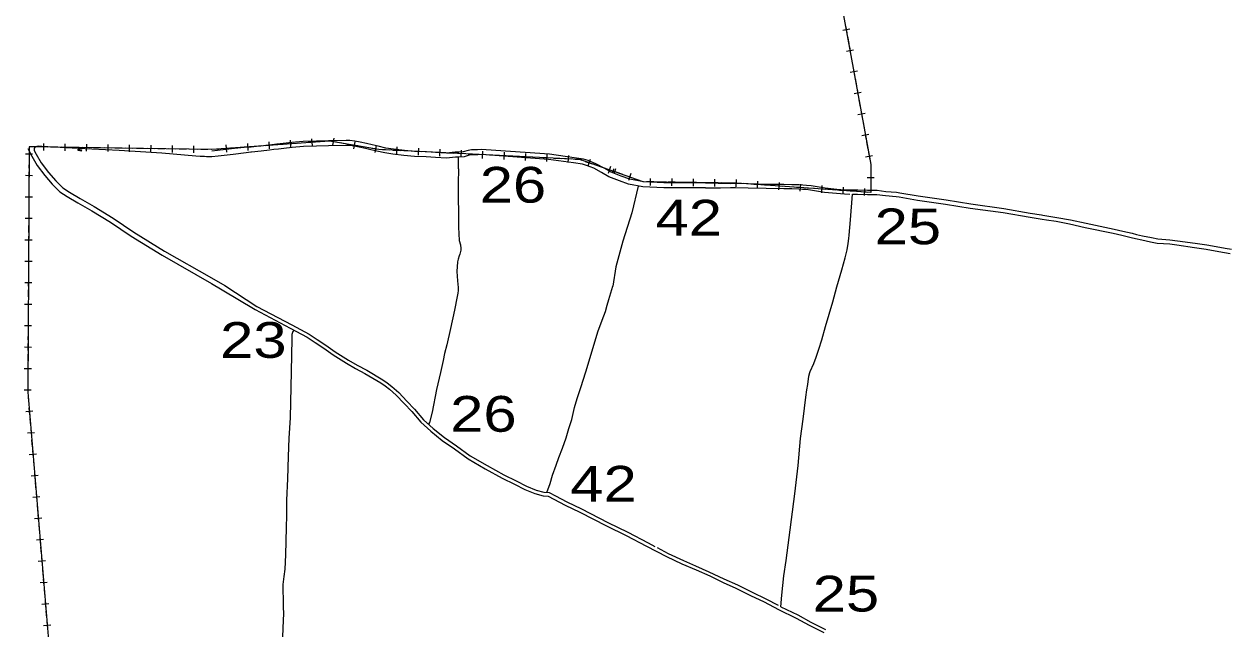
# Model space of a CAD drawing. Extents: x 476989 to 498418, y 4381813 to 4416555.
# Drawn here: x 483846 to 485532, y 4387137 to 4387982 of the extents above; entities that cross this region are included whole.
import ezdxf
from ezdxf.enums import TextEntityAlignment as Align

# ---------------------------------------------------------------- set-up
doc = ezdxf.new("R2010")
doc.units = 0
doc.header["$LTSCALE"] = 20
for name, color, linetype, lineweight in [('13', 7, 'Continuous', 13), ('34', 7, 'Continuous', 13), ('36', 7, 'Continuous', 13), ('38', 7, 'Continuous', 13), ('47', 7, 'Continuous', 13), ('6', 7, 'Continuous', 25)]:
    doc.layers.add(name, color=color, linetype=linetype, lineweight=lineweight)

msp = doc.modelspace()

# ---------------------------------------------------------------- linework, layer by layer
at = {"layer": '34'}
for p, q in [((484990.85, 4387974.21), (485000.69, 4387975.99)), ((484994.88, 4387980.02), (484996.66, 4387970.18)), ((484997.55, 4387965.26), (484999.33, 4387955.42)), ((484996.19, 4387944.69), (485006.03, 4387946.47)), ((485000.22, 4387950.5), (485002, 4387940.66)), ((485002.89, 4387935.74), (485004.67, 4387925.9)), ((485005.56, 4387920.98), (485007.35, 4387911.14)), ((485001.54, 4387915.17), (485011.38, 4387916.95)), ((485008.24, 4387906.22), (485010.02, 4387896.38)), ((485006.88, 4387885.65), (485016.72, 4387887.43)), ((485010.91, 4387891.46), (485012.69, 4387881.62)), ((485013.58, 4387876.7), (485015.36, 4387866.86)), ((485012.22, 4387856.13), (485022.06, 4387857.91)), ((485016.25, 4387861.94), (485018.03, 4387852.1)), ((485018.92, 4387847.18), (485020.71, 4387837.34)), ((484188.13, 4387817.84), (484188.85, 4387807.87)), ((484218.05, 4387820.02), (484218.77, 4387810.04)), ((484247.97, 4387822.19), (484248.69, 4387812.22)), ((484268.28, 4387818.66), (484258.3, 4387817.93)), ((484283.11, 4387817.24), (484273.26, 4387818.95)), ((484279.04, 4387823.02), (484277.33, 4387813.17)), ((484308.6, 4387817.88), (484306.89, 4387808.03)), ((485017.57, 4387826.61), (485027.41, 4387828.39)), ((485021.6, 4387832.42), (485023.38, 4387822.58)), ((485024.27, 4387817.66), (485026.05, 4387807.82)), ((483847.94, 4387801.06), (483857.94, 4387801)), ((483852.97, 4387806.03), (483852.91, 4387796.03)), ((483863.03, 4387810.84), (483853.03, 4387811)), ((483878.03, 4387810.61), (483868.03, 4387810.76)), ((483873.11, 4387815.69), (483872.95, 4387805.69)), ((483893.03, 4387810.37), (483883.03, 4387810.53)), ((483908.02, 4387810.14), (483898.03, 4387810.29)), ((483903.1, 4387815.21), (483902.95, 4387805.22)), ((483923.02, 4387809.9), (483913.02, 4387810.06)), ((483938.02, 4387809.67), (483928.02, 4387809.82)), ((483933.1, 4387814.74), (483932.94, 4387804.75)), ((483953.02, 4387809.43), (483943.02, 4387809.59)), ((483968.02, 4387809.2), (483958.02, 4387809.35)), ((483963.1, 4387814.27), (483962.94, 4387804.27)), ((483983.02, 4387808.96), (483973.02, 4387809.12)), ((483998.01, 4387808.73), (483988.01, 4387808.88)), ((483993.09, 4387813.8), (483992.94, 4387803.8)), ((484013.01, 4387808.49), (484003.01, 4387808.65)), ((484028.01, 4387808.25), (484018.01, 4387808.41)), ((484023.09, 4387813.33), (484022.93, 4387803.33)), ((484043.01, 4387808.02), (484033.01, 4387808.18)), ((484058.01, 4387807.78), (484048.01, 4387807.94)), ((484053.09, 4387812.86), (484052.93, 4387802.86)), ((484073, 4387807.55), (484063.01, 4387807.71)), ((484088, 4387807.31), (484078, 4387807.47)), ((484083.08, 4387812.39), (484082.92, 4387802.39)), ((484103, 4387807.08), (484093, 4387807.24)), ((484108.44, 4387807.03), (484108, 4387807)), ((484118.67, 4387807.78), (484108.7, 4387807.05)), ((484133.63, 4387808.86), (484123.66, 4387808.14)), ((484128.28, 4387813.49), (484129.01, 4387803.51)), ((484148.59, 4387809.95), (484138.62, 4387809.23)), ((484163.55, 4387811.04), (484153.58, 4387810.32)), ((484158.21, 4387815.66), (484158.93, 4387805.69)), ((484178.52, 4387812.13), (484168.54, 4387811.4)), ((484193.48, 4387813.22), (484183.5, 4387812.49)), ((484208.44, 4387814.3), (484198.46, 4387813.58)), ((484223.4, 4387815.39), (484213.42, 4387814.67)), ((484238.36, 4387816.48), (484228.38, 4387815.76)), ((484253.32, 4387817.57), (484243.34, 4387816.84)), ((484297.89, 4387814.67), (484288.04, 4387816.38)), ((484312.67, 4387812.1), (484302.82, 4387813.81)), ((484327.45, 4387809.53), (484317.6, 4387811.24)), ((484338.16, 4387812.74), (484336.44, 4387802.89)), ((484357.21, 4387806.24), (484347.22, 4387806.74)), ((484372.19, 4387805.5), (484362.21, 4387805.99)), ((484367.45, 4387810.74), (484366.95, 4387800.75)), ((484387.17, 4387804.75), (484377.19, 4387805.25)), ((484402.16, 4387804), (484392.17, 4387804.5)), ((484397.41, 4387809.25), (484396.91, 4387799.26)), ((484417.14, 4387803.26), (484407.15, 4387803.75)), ((484432.12, 4387802.51), (484422.13, 4387803.01)), ((484427.37, 4387807.75), (484426.88, 4387797.77)), ((484447.1, 4387801.76), (484437.11, 4387802.26)), ((484462.08, 4387801.02), (484452.09, 4387801.51)), ((484457.34, 4387806.26), (484456.84, 4387796.27)), ((484487.3, 4387804.77), (484486.8, 4387794.78)), ((484517.26, 4387803.27), (484516.76, 4387793.29)), ((484547.22, 4387801.78), (484546.73, 4387791.79)), ((485026.94, 4387802.9), (485028.72, 4387793.06)), ((483852.88, 4387791.03), (483852.83, 4387781.03)), ((484477.06, 4387800.27), (484467.08, 4387800.77)), ((484492.04, 4387799.52), (484482.06, 4387800.02)), ((484507.03, 4387798.78), (484497.04, 4387799.28)), ((484522.01, 4387798.03), (484512.02, 4387798.53)), ((484536.99, 4387797.29), (484527, 4387797.78)), ((484551.97, 4387796.54), (484541.98, 4387797.04)), ((484566.95, 4387795.79), (484556.96, 4387796.29)), ((484581.93, 4387795.05), (484571.95, 4387795.54)), ((484577.19, 4387800.29), (484576.69, 4387790.3)), ((484596.91, 4387794.3), (484586.93, 4387794.8)), ((484611.9, 4387793.55), (484601.91, 4387794.05)), ((484607.15, 4387798.8), (484606.65, 4387788.81)), ((484640.83, 4387786.79), (484631.39, 4387790.08)), ((484637.75, 4387793.16), (484634.46, 4387783.71)), ((484655, 4387781.86), (484645.55, 4387785.14)), ((485022.91, 4387797.09), (485032.75, 4387798.87)), ((483847.77, 4387771.06), (483857.77, 4387771)), ((483852.8, 4387776.03), (483852.74, 4387766.03)), ((484669.16, 4387776.92), (484659.72, 4387780.21)), ((484666.08, 4387783.29), (484662.8, 4387773.84)), ((484683.33, 4387771.99), (484673.88, 4387775.28)), ((484697.49, 4387767.05), (484688.05, 4387770.34)), ((484694.42, 4387773.42), (484691.13, 4387763.98)), ((485025, 4387768.17), (485035, 4387768.17)), ((485030, 4387773.17), (485030, 4387763.17)), ((483852.71, 4387761.03), (483852.65, 4387751.03)), ((484711.66, 4387762.12), (484702.21, 4387765.41)), ((484726.64, 4387761.78), (484716.64, 4387761.93)), ((484721.71, 4387766.85), (484721.56, 4387756.85)), ((484741.63, 4387761.55), (484731.64, 4387761.7)), ((484756.63, 4387761.32), (484746.63, 4387761.47)), ((484751.71, 4387766.39), (484751.56, 4387756.4)), ((484771.63, 4387761.09), (484761.63, 4387761.24)), ((484786.63, 4387760.86), (484776.63, 4387761.01)), ((484781.71, 4387765.94), (484781.55, 4387755.94)), ((484801.63, 4387760.63), (484791.63, 4387760.78)), ((484816.63, 4387760.4), (484806.63, 4387760.56)), ((484811.7, 4387765.48), (484811.55, 4387755.48)), ((484831.62, 4387760.17), (484821.62, 4387760.33)), ((484841.7, 4387765.02), (484841.55, 4387755.02)), ((484861.58, 4387758.71), (484851.6, 4387759.4)), ((484876.54, 4387757.67), (484866.57, 4387758.36)), ((484871.9, 4387763), (484871.21, 4387753.03)), ((484891.5, 4387756.63), (484881.53, 4387757.32)), ((484906.47, 4387755.59), (484896.49, 4387756.28)), ((484901.83, 4387760.92), (484901.13, 4387750.95)), ((484921.43, 4387754.55), (484911.46, 4387755.24)), ((484936.4, 4387753.51), (484926.42, 4387754.2)), ((484931.76, 4387758.84), (484931.06, 4387748.87)), ((484951.36, 4387752.47), (484941.38, 4387753.16)), ((484966.32, 4387751.43), (484956.35, 4387752.12)), ((484961.68, 4387756.76), (484960.99, 4387746.79)), ((484981.29, 4387750.39), (484971.31, 4387751.08)), ((484991.61, 4387754.68), (484990.92, 4387744.7)), ((485021.54, 4387752.6), (485020.85, 4387742.62)), ((485030, 4387758.17), (485030, 4387748.17)), ((483847.59, 4387741.06), (483857.59, 4387741)), ((483852.62, 4387746.03), (483852.56, 4387736.03)), ((484996.25, 4387749.35), (484986.28, 4387750.04)), ((485011.22, 4387748.31), (485001.24, 4387749)), ((485026.18, 4387747.27), (485016.2, 4387747.96)), ((483852.53, 4387731.03), (483852.48, 4387721.03)), ((483847.42, 4387711.06), (483857.42, 4387711)), ((483852.36, 4387701.03), (483852.3, 4387691.03)), ((483852.45, 4387716.03), (483852.39, 4387706.03)), ((483852.27, 4387686.03), (483852.21, 4387676.03)), ((483847.24, 4387681.06), (483857.24, 4387681)), ((483852.18, 4387671.03), (483852.13, 4387661.03)), ((483847.07, 4387651.06), (483857.07, 4387651)), ((483852.1, 4387656.03), (483852.04, 4387646.03)), ((483852.01, 4387641.03), (483851.95, 4387631.03)), ((483846.89, 4387621.06), (483856.89, 4387621.01)), ((483851.92, 4387626.03), (483851.86, 4387616.03)), ((483851.83, 4387611.03), (483851.78, 4387601.03)), ((483846.72, 4387591.06), (483856.72, 4387591.01)), ((483851.75, 4387596.04), (483851.69, 4387586.04)), ((483851.57, 4387566.04), (483851.51, 4387556.04)), ((483851.66, 4387581.04), (483851.6, 4387571.04)), ((483846.54, 4387561.06), (483856.54, 4387561.01)), ((483851.48, 4387551.04), (483851.43, 4387541.04)), ((483846.37, 4387531.07), (483856.37, 4387531.01)), ((483851.4, 4387536.04), (483851.34, 4387526.04)), ((483851.31, 4387521.04), (483851.25, 4387511.04)), ((483846.19, 4387501.07), (483856.19, 4387501.01)), ((483851.22, 4387506.04), (483851.16, 4387496.04)), ((483851.13, 4387491.04), (483851.08, 4387481.04)), ((483846.02, 4387471.07), (483856.02, 4387471.01)), ((483851.58, 4387461.06), (483852.41, 4387451.1)), ((483848.26, 4387440.71), (483858.23, 4387441.55)), ((483852.83, 4387446.11), (483853.66, 4387436.15)), ((483854.08, 4387431.17), (483854.91, 4387421.2)), ((483855.33, 4387416.22), (483856.16, 4387406.25)), ((483850.76, 4387410.82), (483860.72, 4387411.65)), ((483856.57, 4387401.27), (483857.41, 4387391.3)), ((483853.26, 4387380.92), (483863.22, 4387381.76)), ((483857.82, 4387386.32), (483858.65, 4387376.36)), ((483859.07, 4387371.37), (483859.9, 4387361.41)), ((483855.75, 4387351.03), (483865.72, 4387351.86)), ((483860.32, 4387356.43), (483861.15, 4387346.46)), ((483861.57, 4387341.48), (483862.4, 4387331.51)), ((483858.25, 4387321.13), (483868.22, 4387321.96)), ((483862.82, 4387326.53), (483863.65, 4387316.56)), ((483864.07, 4387311.58), (483864.9, 4387301.62)), ((483865.31, 4387296.63), (483866.15, 4387286.67)), ((483860.75, 4387291.24), (483870.71, 4387292.07)), ((483866.56, 4387281.69), (483867.39, 4387271.72)), ((483863.24, 4387261.34), (483873.21, 4387262.17)), ((483867.81, 4387266.74), (483868.64, 4387256.77)), ((483869.06, 4387251.79), (483869.89, 4387241.82)), ((483865.74, 4387231.44), (483875.71, 4387232.28)), ((483870.31, 4387236.84), (483871.14, 4387226.88)), ((483871.56, 4387221.89), (483872.39, 4387211.93)), ((483868.24, 4387201.55), (483878.2, 4387202.38)), ((483872.8, 4387206.95), (483873.64, 4387196.98)), ((483874.05, 4387192), (483874.89, 4387182.03)), ((483875.3, 4387177.05), (483876.13, 4387167.09)), ((483870.74, 4387171.65), (483880.7, 4387172.48)), ((483876.55, 4387162.1), (483877.38, 4387152.14)), ((483877.8, 4387147.15), (483878.63, 4387137.19)), ((483873.23, 4387141.76), (483883.2, 4387142.59))]:
    msp.add_line(p, q, dxfattribs=at)
for points in [[(484742, 4388368), (484968, 4388081), (484988, 4388018), (485030, 4387786), (485030, 4387747), (484843, 4387760), (484712, 4387762), (484623, 4387793), (484342, 4387807), (484273, 4387819), (484108.44, 4387807.03)], [(484108, 4387807), (483853, 4387811), (483851, 4387468), (483887, 4387037), (483872.5, 4386448.65)], [(484342.23, 4387806.99), (484342, 4387807), (484332.37, 4387808.67)], [(484626.67, 4387791.72), (484623, 4387793), (484616.89, 4387793.3)], [(485029.61, 4387788.14), (485030, 4387786), (485030, 4387778.17)], [(484846.61, 4387759.75), (484843, 4387760), (484836.62, 4387760.1)], [(483851.05, 4387476.04), (483851, 4387468), (483851.16, 4387466.04)]]:
    msp.add_lwpolyline(points, dxfattribs=at)
at = {"layer": '36'}
for p, q in [((484108.03, 4387619.81), (484123.22, 4387611.07)), ((484108.05, 4387627.5), (484126.55, 4387616.86))]:
    msp.add_line(p, q, dxfattribs=at)
for points in [[(484492.14, 4387806.72), (484486.14, 4387806.96), (484480.32, 4387806.84), (484476.34, 4387806.76), (484471.87, 4387806.54), (484467.1, 4387806), (484460.07, 4387803.89), (484453.81, 4387803.31), (484448.89, 4387803.21), (484436.69, 4387802.24), (484421.56, 4387802.76), (484408.78, 4387803.86), (484392.62, 4387804.33), (484377.91, 4387805.83), (484362.6, 4387807.61), (484351.87, 4387809.25), (484341.04, 4387811.67), (484332.68, 4387813.54), (484324.9, 4387815.4), (484316.04, 4387817.5), (484308.68, 4387818.74), (484301.73, 4387819.68), (484296.23, 4387819.57), (484271.85, 4387819.17), (484254.85, 4387819.04), (484236.24, 4387818.52), (484220.25, 4387816.99), (484208.34, 4387815.67), (484199.57, 4387814.74), (484192.4, 4387813.48), (484184.31, 4387812.87), (484177.12, 4387811.96), (484174.63, 4387811.68)], [(483851.03, 4387808.55), (483857.01, 4387797.7), (483864.1, 4387784.71), (483874.77, 4387770.68), (483885.4, 4387758.59), (483896.2, 4387748.15), (483906.03, 4387741.65), (483921.28, 4387732.7), (483940.8, 4387721.55), (483967.05, 4387705.4), (483995.93, 4387685.76), (484039.14, 4387659.45), (484108.03, 4387619.81)], [(483870.96, 4387811.4), (483866.44, 4387811.67), (483863.59, 4387811.57), (483861.49, 4387811.04), (483860.51, 4387809.56), (483860.05, 4387807.95), (483860.05, 4387806.82), (483860.27, 4387805.88)], [(483860.27, 4387805.88), (483862.88, 4387800.87), (483869.72, 4387788.35), (483879.94, 4387774.91), (483890.24, 4387763.2), (483900.4, 4387753.38), (483909.57, 4387747.32), (483924.63, 4387738.47), (483944.21, 4387727.3), (483970.67, 4387711.01), (483999.55, 4387691.37), (484042.54, 4387665.2), (484108.05, 4387627.5)], [(484108.42, 4387797.03), (484101.21, 4387797.11), (484098.2, 4387797.19), (484092.4, 4387797.41), (484086.08, 4387797.87), (484038.5, 4387802.12), (483979.17, 4387805.81), (483921.64, 4387808.76), (483870.96, 4387811.4)], [(484491.86, 4387799.73), (484486.07, 4387799.96), (484480.46, 4387799.85), (484476.58, 4387799.77), (484472.44, 4387799.57), (484468.51, 4387799.12), (484461.41, 4387796.99), (484454.21, 4387796.32), (484449.24, 4387796.22), (484436.85, 4387795.24), (484421.14, 4387795.78), (484408.38, 4387796.87), (484392.16, 4387797.35), (484377.15, 4387798.88), (484361.67, 4387800.68), (484350.58, 4387802.37), (484339.52, 4387804.85), (484331.1, 4387806.73), (484323.28, 4387808.6), (484314.65, 4387810.64), (484307.63, 4387811.82), (484301.33, 4387812.68), (484296.36, 4387812.58), (484271.93, 4387812.18), (484254.98, 4387812.05), (484236.67, 4387811.54), (484220.97, 4387810.03), (484209.3, 4387808.74), (484201.82, 4387807.75), (484195.07, 4387807.06), (484189.06, 4387806.36), (484177.76, 4387804.99), (484164.03, 4387803.43), (484162.95, 4387803.36), (484156.54, 4387802.4), (484138.3, 4387800.35), (484117.28, 4387798.01), (484108.42, 4387797.03)], [(484174.63, 4387811.68), (484163.41, 4387810.4), (484162.48, 4387810.34), (484153.9, 4387809.75), (484136.02, 4387807.99), (484116.51, 4387805.89), (484108.43, 4387804.72)], [(484798.93, 4387760.7), (484740.89, 4387760.52), (484712.35, 4387761.9), (484693.08, 4387765.5), (484681.23, 4387769.77), (484666.83, 4387775.25), (484657.12, 4387781), (484645.83, 4387787.32), (484634.93, 4387791.59), (484628.34, 4387793.7), (484615.13, 4387795.49), (484580.58, 4387800.8), (484492.14, 4387806.72)], [(484798.95, 4387753.61), (484740.73, 4387753.43), (484711.52, 4387754.84), (484691.22, 4387758.64), (484678.76, 4387763.13), (484663.74, 4387768.84), (484653.58, 4387774.86), (484642.8, 4387780.89), (484632.55, 4387784.9), (484626.77, 4387786.76), (484614.38, 4387788.44), (484579.29, 4387793.34), (484491.86, 4387799.73)], [(484798.93, 4387760.7), (484834.03, 4387759.68), (484840.94, 4387759.89), (484858.69, 4387759.43), (484883.86, 4387758.86), (484908.49, 4387758.47), (484919.79, 4387758.31), (484929.83, 4387758.04), (484934.93, 4387757.78), (484940.17, 4387757.35), (484946.81, 4387756.64), (484966.32, 4387753.46), (484982.82, 4387751.87), (484993.84, 4387750.94), (485001.08, 4387750.58), (485011.81, 4387750.66), (485025.45, 4387750.29), (485038.89, 4387750.19), (485051.42, 4387748.65), (485066.32, 4387747.42), (485070.86, 4387746.77), (485096.5, 4387742.28), (485135.5, 4387736.71), (485170.14, 4387731.03), (485216.24, 4387724.72), (485253.12, 4387718.26), (485268.79, 4387715.93), (485270.96, 4387715.52), (485290.18, 4387712.13), (485309.62, 4387708.84), (485331.43, 4387704.04), (485370.49, 4387695.9), (485382.54, 4387692.96), (485395.76, 4387690.01), (485401.7, 4387688.38), (485410.35, 4387686.48), (485422.59, 4387683.93), (485431.58, 4387682.19), (485448.2, 4387681.05)], [(484798.95, 4387753.61), (484820.12, 4387753.58), (484834.17, 4387753.81), (484840.95, 4387754.01), (484858.55, 4387753.56), (484883.74, 4387752.99), (484908.41, 4387752.6), (484919.67, 4387752.44), (484929.6, 4387752.17), (484934.54, 4387751.92), (484939.61, 4387751.5), (484946.03, 4387750.81), (484965.57, 4387747.63), (484982.29, 4387746.02), (484993.45, 4387745.08), (485000.69, 4387744.72)], [(485004.65, 4387744.73), (485011.76, 4387744.78), (485025.35, 4387744.41), (485038.51, 4387744.32), (485050.82, 4387742.8), (485065.65, 4387741.58), (485069.93, 4387740.96), (485095.58, 4387736.47), (485134.61, 4387730.9), (485169.26, 4387725.22), (485215.38, 4387718.9), (485253.12, 4387712.35), (485269.91, 4387709.7), (485276.03, 4387708.96), (485289.33, 4387706.75), (485308.29, 4387703.12), (485330.2, 4387698.29), (485369.19, 4387690.16), (485381.21, 4387687.24), (485394.34, 4387684.31), (485400.29, 4387682.67), (485409.12, 4387680.73), (485421.43, 4387678.16), (485430.75, 4387676.36), (485448.2, 4387675.12)], [(485448.2, 4387681.05), (485458.98, 4387679.52), (485483.62, 4387676.09), (485499.96, 4387673.83), (485513.05, 4387671.47), (485525.85, 4387669.03), (485534.71, 4387667.62)], [(485448.2, 4387675.12), (485458.17, 4387673.7), (485482.82, 4387670.27), (485499.03, 4387668.02), (485511.98, 4387665.69), (485524.84, 4387663.24), (485532.77, 4387661.98)], [(484126.55, 4387616.86), (484171.56, 4387587.69), (484220.56, 4387561.88), (484244.55, 4387549.14), (484255.68, 4387541.67), (484268.12, 4387533.64), (484280.94, 4387524.46), (484299.66, 4387512.73), (484312.04, 4387505.62), (484325.17, 4387498.5), (484347.5, 4387485.15), (484353.9, 4387480.89), (484360.39, 4387475.99), (484369.97, 4387467.47), (484381.34, 4387455.3), (484391.96, 4387444.02), (484404.4, 4387429.24), (484417.97, 4387417.02), (484433.78, 4387404.44), (484450.68, 4387392.61), (484469.89, 4387379.04), (484493.44, 4387365.2), (484517.03, 4387352.17), (484534.33, 4387343.66), (484548.49, 4387336.61), (484562.01, 4387330.96), (484572.76, 4387328.16), (484580.5, 4387327.48), (484589.4, 4387322.8), (484605.22, 4387314.52), (484625.5, 4387304.54), (484662.61, 4387285.63)], [(484123.22, 4387611.07), (484169.09, 4387583.22), (484218.18, 4387557.37), (484241.92, 4387544.76), (484252.87, 4387537.41), (484265.25, 4387529.42), (484278.09, 4387520.22), (484297.03, 4387508.36), (484309.55, 4387501.16), (484322.57, 4387494.1), (484344.86, 4387480.78), (484350.95, 4387476.73), (484357.15, 4387472.04), (484366.41, 4387463.82), (484377.62, 4387451.81), (484388.15, 4387440.62), (484400.73, 4387425.69), (484414.67, 4387413.12), (484430.73, 4387400.34), (484447.75, 4387388.44), (484467.12, 4387374.75), (484490.91, 4387360.77), (484514.67, 4387347.64), (484532.07, 4387339.08), (484546.36, 4387331.96), (484560.38, 4387326.12), (484571.88, 4387323.12), (484579.03, 4387322.49), (484587.03, 4387318.28), (484602.91, 4387309.97), (484623.22, 4387299.98), (484660.3, 4387281.08)], [(484660.3, 4387281.08), (484688, 4387267.44), (484716.6, 4387252.46), (484744.57, 4387237.87), (484765.96, 4387228.04), (484785.95, 4387219.5), (484804.94, 4387211.05), (484823.92, 4387201.9), (484841.33, 4387193.76), (484861.92, 4387183.47), (484880.95, 4387174.47), (484900.92, 4387163.88), (484925.9, 4387151.85), (484944.1, 4387141.99), (484964.47, 4387131.61)], [(484662.61, 4387285.63), (484690.3, 4387271.97), (484718.95, 4387256.96), (484728.09, 4387252.19)], [(484731.26, 4387250.54), (484746.8, 4387242.43), (484768.02, 4387232.68), (484785.12, 4387224.95), (484803.58, 4387216.58), (484824.62, 4387206.9), (484843.61, 4387198.29), (484864.14, 4387188.04), (484883.22, 4387179.01), (484900.49, 4387169.86)], [(484904.27, 4387167.9), (484928.21, 4387156.37), (484946.46, 4387146.48), (484966.73, 4387136.15)]]:
    msp.add_lwpolyline(points, dxfattribs=at)
at = {"layer": '38'}
for points in [[(484670.16, 4387780.04), (484669.72, 4387777.82), (484669.1, 4387775.84), (484668.65, 4387774.56)], [(484672.94, 4387780.04), (484672.11, 4387777.17), (484671.45, 4387775.07), (484670.96, 4387773.68)]]:
    msp.add_lwpolyline(points, dxfattribs=at)
at = {"layer": '47'}
msp.add_lwpolyline([(483921.8, 4387807.72), (483926.14, 4387806.91), (483925.75, 4387804.81), (483921.41, 4387805.62)], close=True, dxfattribs=at)
at = {"layer": '6'}
for points in [[(484453.47, 4387780.04), (484453.47, 4387780.1), (484453.58, 4387783.24), (484453.64, 4387789.5), (484453.63, 4387794.48), (484453.5, 4387796.31)], [(484453.47, 4387780.04), (484453.08, 4387759.69), (484453.48, 4387698.54), (484454.48, 4387679.81), (484456.12, 4387674), (484456.9, 4387668.86), (484456.87, 4387666.47), (484455.63, 4387660.65), (484454.55, 4387658.51), (484452.98, 4387653.95), (484452.22, 4387649.97), (484451.33, 4387636.56), (484451.92, 4387623.52)], [(484704.97, 4387756.07), (484696.13, 4387718.73), (484683.45, 4387678.89), (484673.62, 4387643.09), (484669.2, 4387615.95)], [(484904.27, 4387167.9), (484905.66, 4387183.86), (484908.57, 4387210.82), (484911.66, 4387232.66), (484916.02, 4387264.71), (484923.85, 4387325.72), (484928.6, 4387365.22), (484931.97, 4387402.9), (484935.53, 4387430.32), (484939.12, 4387461.07), (484940.92, 4387470.98), (484942.02, 4387478.39), (484943.44, 4387490.05), (484944.88, 4387495.32), (484945.51, 4387496.66), (484950.42, 4387507.8), (484953.76, 4387516.7), (484957.52, 4387528.13), (484961.56, 4387540.98), (484966.88, 4387559.67), (484976.87, 4387594.07), (484982.74, 4387615.17), (484989.84, 4387639.07), (484994.09, 4387655.51), (484996.91, 4387666.98), (484998.31, 4387675.88), (484999.26, 4387682.75), (484999.77, 4387687.23), (485001.75, 4387708.92), (485004.65, 4387744.73)], [(484451.92, 4387623.52), (484452.86, 4387614.05), (484453.01, 4387610), (484452.55, 4387606.44), (484451.76, 4387601.75), (484447.74, 4387582.4), (484442.3, 4387556.91), (484437.07, 4387533.96), (484434.1, 4387522.04), (484431.88, 4387512.33), (484428.54, 4387495.55), (484422.91, 4387471.62), (484416.7, 4387439.75), (484413.14, 4387425.44), (484411.42, 4387422.97)], [(484577.29, 4387327.76), (484581.51, 4387340.01), (484585.22, 4387351.76), (484589.98, 4387365.78), (484593.96, 4387376.29), (484599.05, 4387389.6), (484604.12, 4387403.9), (484608.08, 4387416.92), (484611.88, 4387429.64), (484616, 4387446.57), (484619.45, 4387459.1), (484624.49, 4387474.46), (484631.82, 4387496.43), (484639.03, 4387521.01), (484648.61, 4387552), (484654.53, 4387568.76), (484658.91, 4387580.79), (484661.5, 4387589.61), (484663.81, 4387597.41), (484669.2, 4387615.95)], [(484223.21, 4387554.7), (484222.02, 4387552.66), (484220.97, 4387549.9), (484220.49, 4387548.37), (484220.38, 4387546.67), (484220.49, 4387542.58), (484219.52, 4387496.61), (484218.07, 4387431.96), (484216.06, 4387403.37), (484215.34, 4387378.04), (484214.43, 4387346.88), (484213.17, 4387316.65), (484212.78, 4387295.39)], [(484212.82, 4387295.28), (484212.47, 4387278.4), (484211.44, 4387240.58), (484210.65, 4387220.54), (484209.3, 4387209.89), (484208.08, 4387198.84), (484207.98, 4387189.84), (484208.12, 4387179.31), (484208.42, 4387167.67), (484208.7, 4387158.03), (484208.44, 4387149.25), (484207.87, 4387137.58), (484207.04, 4387114.72), (484205.45, 4387091.7), (484204.57, 4387075.39), (484204.95, 4387059.47), (484204.36, 4387036.27), (484203.86, 4387018.17), (484202.77, 4387002.21), (484201.65, 4386984.79), (484200.05, 4386972.86), (484199.05, 4386967.22), (484197.58, 4386960.92), (484197.34, 4386960.26)]]:
    msp.add_lwpolyline(points, dxfattribs=at)

# ---------------------------------------------------------------- texts
at = {"layer": '13', "width": 1.25}
for s, p in [('26', (484529.7, 4387732.85)), ('42', (484775.6, 4387686.81)), ('25', (485081.99, 4387674.67)), ('23', (484166.66, 4387515.84)), ('26', (484488.37, 4387412.52)), ('42', (484656.35, 4387314.78)), ('25', (484995.38, 4387161.14))]:
    msp.add_text(s, height=50, dxfattribs=at).set_placement(p, align=Align.CENTER)

doc.saveas('drawing.dxf')
